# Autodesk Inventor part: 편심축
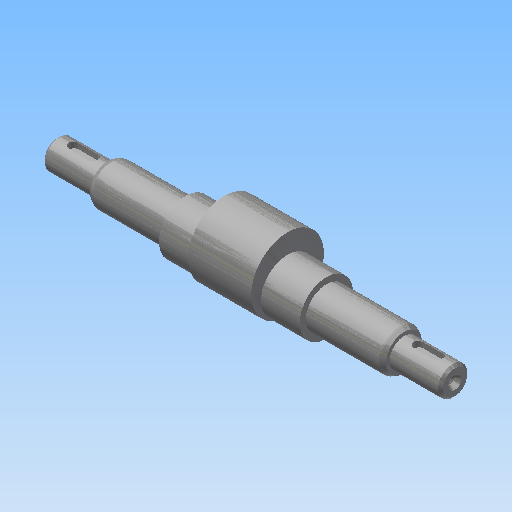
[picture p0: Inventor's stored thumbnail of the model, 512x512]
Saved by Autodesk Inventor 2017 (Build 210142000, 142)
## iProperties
Created: 2019-01
Part Number: 편심축
Material: 강철, 연강
Document SubType Name: Modeling
Designer: mduedu
Density: 7.86 g/cm^3
Mass: 387.265 g
Surface Area: 112.621 cm^2
Volume: 49.2703 cm^3
Appearance: 강철
Author: mduedu
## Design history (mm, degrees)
sketch "스케치1"
  geometry: L1 (0, 0)-(21, 0); L2 (21, 0)-(21, 6); L3 (21, 6)-(0, 6); L4 (0, 6)-(0, 0); L5 (21, 0)-(53, 0); L6 (53, 0)-(53, 8.5); L7 (53, 8.5)-(21, 8.5); L8 (21, 8.5)-(21, 0); L9 (53, 0)-(111, 0); L10 (111, 0)-(111, 11); L11 (111, 11)-(53, 11); L12 (53, 11)-(53, 0); L13 (82, 11)-(82, 0); L14 (111, 0)-(143, 0); L15 (143, 0)-(143, 8.5); L16 (143, 8.5)-(111, 8.5); L17 (111, 8.5)-(111, 0); L18 (143, 0)-(164, 0); L19 (164, 0)-(164, 6); L20 (164, 6)-(143, 6); L21 (143, 6)-(143, 0)
  constraints: 42 end point, 10 parallel, 5 horizontal, 5 perpendicular, 4 collinear, 2 midpoint
  dimensions: "d3" = 58 distance of L10.end L11.end; "d5" = 12 diameter of L3 L1; "d6" = 17 diameter of L7 L5; "d8" = 22 diameter of L11 L9; "d51" = 164 distance between parallel lines of L4 L19; "d52" = 122 distance between parallel lines of L2 L15; "d53" = 32 distance of L15.end L16.end (derived); "d54" = 32 distance of L6.end L7.end (derived)
revolve "회전1" sketch "스케치1" stored, may be unused: angle "d9" = 90 deg
node "작업 평면3"
sketch "스케치2"
  geometry: C1 r 15 at (0, 4); C2 r 11 at (0, 0); 1 further point
  constraints: 2 centre point, 1 tangent, 1 vertical alignment
  dimensions: "d11" = 4 distance of point (0, 0) C1.centre
extrude "돌출1" join sketch "스케치2" distance "d12" = 26; taper "d13" = 0 deg
node "작업 평면2"
sketch "스케치3" dims "d16" = 12
  geometry: L1 (-4.5, 2)-(3.5, 2); L2 (3.5, 2)-(3.5, -2); L3 (3.5, -2)-(-4.5, -2); L4 (-4.5, -2)-(-4.5, 2); L5 (-10.5, 8.5)-(-10.5, -8.5) reference; 3 further points
  constraints: 8 end point, 2 midpoint, 2 parallel, 2 vertical alignment, 1 horizontal, 1 horizontal alignment, 1 perpendicular, 4 other
  dimensions: "d14" = 4 distance between parallel lines of L3 L1; "d17" = 4 dimension on L5
extrude "돌출2" cut sketch "스케치3" distance "d18" = 2.5; taper "d19" = 0 deg
node "작업 평면4"
chamfer "모따기1" distance "d20" = 1.82; stored, may be unused: second distance "d21" = 2, angle "d22" = 30 deg
chamfer "모따기3" distance "d56" = 1.82; stored, may be unused: second distance "d57" = 2, angle "d58" = 30 deg
fillet "모깎기1" dims "d23" = 2
hole "구멍2" diameter "d39" = 3.242; stored, may be unused: countersink angle "d43" = 60 deg, drill point angle "d45" = 118 deg; dims "d37" = 10, "d38" = 10, "d40" = 8, "d41" = 5.51, "d42" = 2, "d44" = 10
sketch "스케치5"
  geometry: L1 (0, 0)-(2, 0); L2 (2, 0)-(2, 1.621); L3 (0, 2.776)-(0, 0); L4 (0, 2.776)-(2, 1.621); L5 (10, 1.621)-(0, 1.621) reference
  constraints: 8 end point, 1 horizontal, 1 parallel, 1 perpendicular, 1 point on line
  dimensions: "d46" = 2 distance between parallel lines of L2 L3; "d48" = 30 deg angle of L4 L1
revolve "회전2" sketch "스케치5" stored, may be unused: angle "d50" = 90 deg
chamfer "모따기2" distance "d25" = 1; stored, may be unused: second distance "d26" = 2, angle "d27" = 30 deg
node "솔리드1"
mirror "대칭1"
mirror "대칭2"
mirror "대칭3"
other parameters: "d55" = -16
